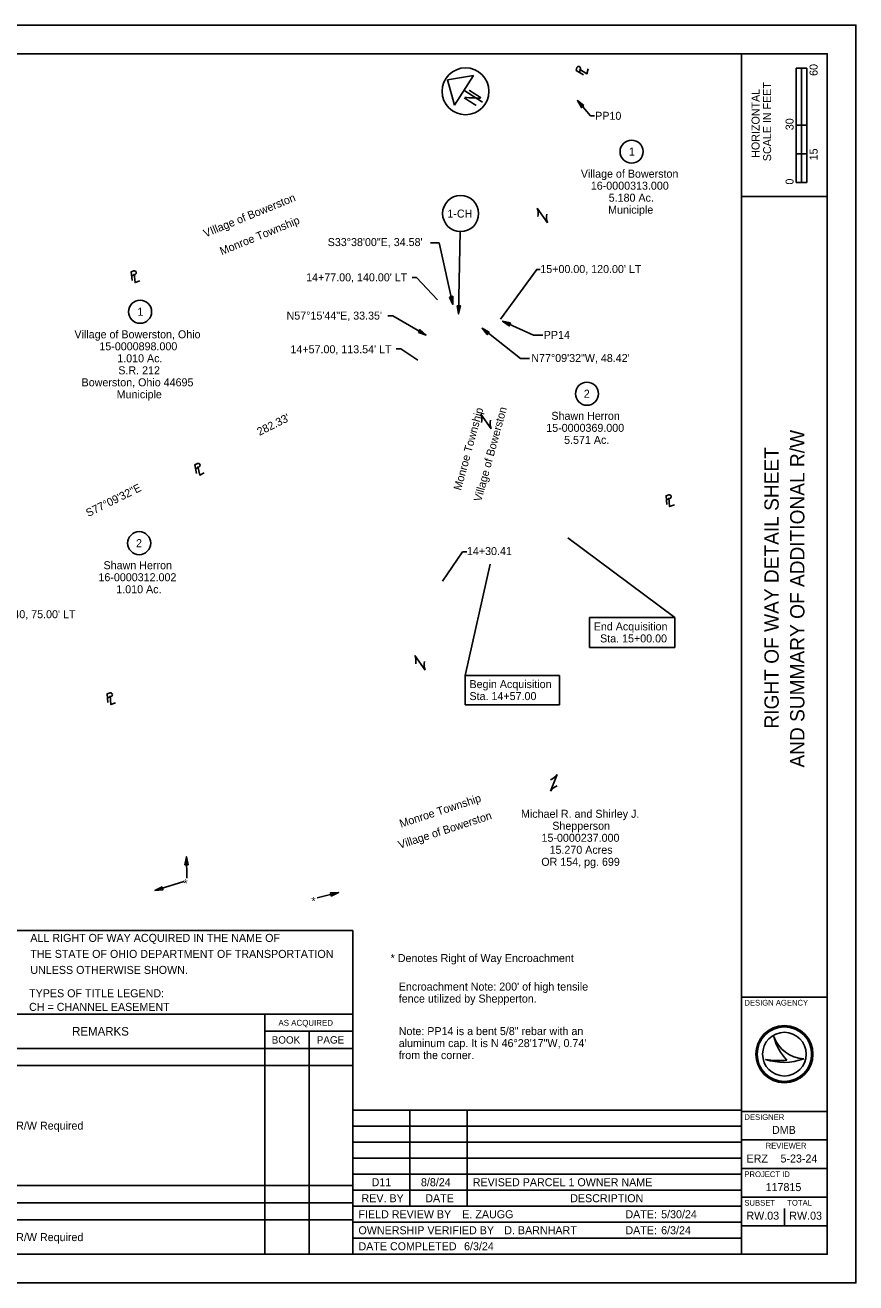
# Model space of a CAD drawing. Extents: x 0 to 1644, y -86 to 660.
# Drawn here: x 584 to 1020, y 0 to 660 of the extents above; entities that cross this region are included whole.
import ezdxf

# ---------------------------------------------------------------- set-up
doc = ezdxf.new("R2010")
doc.units = 0
for name, color, linetype in [('Default', 7, 'Continuous'), ('RW_X_Text', 7, 'Continuous'), ('SH_Border', 7, 'Continuous'), ('SH_Cut_Line', 7, 'Continuous'), ('SH_Data', 7, 'Continuous'), ('SH_Text', 7, 'Continuous'), ('UT_X_Water_Cells', 7, 'Continuous'), ('VG_X_Cells', 7, 'Continuous')]:
    doc.layers.add(name, color=color, linetype=linetype)

msp = doc.modelspace()

# ---------------------------------------------------------------- linework, layer by layer
at = {"layer": 'Default'}
for p, q in [((45, 184.85), (755.9, 184.85)), ((755.9, 184.85), (755.9, 60))]:
    msp.add_line(p, q, dxfattribs=at)
at = {"layer": 'SH_Border'}
for p, q in [((960, 15), (960, 645)), ((960, 570), (1005, 570)), ((960, 150), (1005, 150)), ((960, 90), (1005, 90)), ((960, 75), (1005, 75)), ((960, 60), (1005, 60)), ((960, 45), (1005, 45)), ((960, 30), (1005, 30))]:
    msp.add_line(p, q, dxfattribs=at)
msp.add_lwpolyline([(45, 645), (1005, 645), (1005, 15), (45, 15)], close=True, dxfattribs=at)
at = {"layer": 'SH_Cut_Line'}
msp.add_lwpolyline([(0, 0), (1020, 0), (1020, 660), (0, 660)], close=True, dxfattribs=at)
at = {"layer": 'SH_Data'}
for p, q in [((988.7, 577.5), (988.7, 637.5)), ((994.32, 637.5), (988.7, 637.5)), ((988.7, 607.5), (988.7, 637.5)), ((988.7, 637.5), (991.5, 637.5)), ((991.5, 637.5), (991.52, 637.5)), ((991.52, 637.5), (991.52, 607.5)), ((994.32, 637.5), (994.32, 577.5)), ((991.52, 607.5), (988.7, 607.5)), ((994.3, 607.5), (991.5, 607.5)), ((991.5, 607.5), (991.5, 592.5)), ((994.3, 592.5), (994.3, 607.5)), ((991.5, 592.5), (988.7, 592.5)), ((988.7, 592.5), (988.7, 577.5)), ((991.5, 577.5), (991.5, 592.5)), ((991.5, 592.5), (994.3, 592.5)), ((994.32, 577.5), (988.7, 577.5)), ((988.7, 577.5), (991.5, 577.5)), ((45, 141), (755.9, 141)), ((709.75, 141), (709.75, 15)), ((709.75, 132), (755.9, 132)), ((733, 132), (733, 15)), ((977.02, 129.29), (977.02, 129.29)), ((45, 123), (755.9, 123)), ((982.5, 120), (982.5, 120)), ((45, 114), (755.9, 114)), ((972.52, 117.29), (972.51, 117.29)), ((992.62, 117.56), (992.62, 117.56)), ((45, 51), (755.9, 51)), ((45, 42), (755.9, 42)), ((45, 33), (755.9, 33)), ((982.5, 30), (982.5, 39))]:
    msp.add_line(p, q, dxfattribs=at)
for radius in [15, 14.3, 14.3, 11.47]:
    msp.add_circle((982.5, 120), radius, dxfattribs=at)
for centre, radius, start, end in [((993.48, 134.93), 17.4, 198.92567, 198.93195), ((1000.4, 134.1), 23.87, 191.63793, 191.64215), ((993.48, 134.93), 17.4, 198.93195, 267.16574), ((1000.4, 134.1), 23.87, 191.64215, 226.09467), ((982.18, 146.1), 30.39, 251.45274, 251.45764), ((982.18, 146.1), 30.39, 251.45764, 290.08324), ((979.44, 154.63), 37.98, 259.49639, 259.49952), ((979.44, 154.63), 37.98, 259.49952, 276.66723)]:
    msp.add_arc(centre, radius, start, end, dxfattribs=at)
at = {"layer": 'SH_Text'}
for p, q in [((819.26, 633.61), (805.66, 631.34)), ((809.33, 618.05), (819.26, 633.61)), ((805.66, 631.34), (809.33, 618.05)), ((814.29, 625.83), (824.07, 619.58)), ((812.34, 551.65), (811.49, 508.45)), ((924.98, 349.08), (868.73, 391.04)), ((814.94, 318.8), (828.03, 377.17)), ((924.98, 349.08), (880.21, 349.08)), ((880.21, 349.08), (880.21, 333.46)), ((924.98, 349.08), (924.98, 333.46)), ((924.98, 333.46), (880.21, 333.46)), ((814.94, 318.8), (814.94, 303.27)), ((814.94, 318.8), (864.35, 318.8)), ((864.35, 318.8), (864.35, 303.27)), ((814.94, 303.27), (864.35, 303.27)), ((668.72, 212.36), (668.59, 223.62)), ((667.27, 210.55), (652.01, 205.85)), ((737.3, 202.04), (748.48, 204.83)), ((755.9, 90.6), (755.9, 15)), ((755.9, 90.6), (960, 90.6)), ((785.9, 90.6), (785.9, 40.2)), ((815.9, 90.6), (815.9, 40.2)), ((755.9, 82.2), (960, 82.2)), ((755.9, 73.8), (960, 73.8)), ((755.9, 65.4), (960, 65.4)), ((755.9, 57), (960, 57)), ((755.9, 48.6), (960, 48.6)), ((755.9, 40.2), (960, 40.2)), ((755.9, 31.8), (960, 31.8)), ((755.9, 23.4), (960, 23.4)), ((960, 15), (960, 15))]:
    msp.add_line(p, q, dxfattribs=at)
for points in [[(882.76, 612.49), (880.62, 612.46), (873.86, 620.46)], [(796.69, 545.71), (801.25, 545.71), (808.51, 513.42)], [(854.3, 531.81), (852.5, 531.81), (833.47, 505.75)], [(787.05, 527.55), (789.4, 527.55), (800.32, 515.83)], [(774.36, 507.49), (776.92, 507.49), (794.4, 497.39)], [(855.67, 497.35), (850.82, 497.35), (834.54, 504.66)], [(848.72, 485.02), (843.87, 485.02), (823.76, 500.92)], [(778.69, 490.07), (781.18, 490.07), (790.12, 484.19)], [(815.78, 383.56), (813.58, 383.56), (802.96, 368.29)]]:
    msp.add_lwpolyline(points, dxfattribs=at)
for points in [[(877.21, 617.79), (875.93, 616.71), (873.86, 620.46)], [(806.77, 517.34), (808.41, 517.71), (808.51, 513.42)], [(810.73, 512.66), (812.41, 512.63), (811.49, 508.45)], [(838.72, 503.7), (838.03, 502.17), (834.54, 504.66)], [(790.35, 498.76), (791.19, 500.22), (794.4, 497.39)], [(827.57, 498.97), (826.53, 497.66), (823.76, 500.92)], [(669.47, 219.43), (667.79, 219.41), (668.59, 223.62)], [(655.78, 207.89), (656.27, 206.29), (652.01, 205.85)], [(744.6, 203), (744.2, 204.63), (748.48, 204.83)]]:
    msp.add_lwpolyline(points, close=True, dxfattribs=at)
for centre, radius in [((815.11, 625.3), 12.3), ((902.26, 593.63), 6.05), ((812.52, 561.11), 9.46), ((644.27, 509.58), 6.05), ((878.85, 466.56), 6.05), ((643.77, 388.16), 6.05)]:
    msp.add_circle(centre, radius, dxfattribs=at)
at = {"layer": 'UT_X_Water_Cells'}
msp.add_circle((815.11, 625.3), 12.3, dxfattribs=at)
at = {"layer": 'VG_X_Cells'}
for p, q in [((874.94, 635.16), (875.45, 637.03)), ((876.16, 636.07), (876.16, 636.07)), ((858.1, 556.35), (852.74, 564.04)), ((855.42, 560.19), (855.42, 560.19)), ((639.81, 528.37), (641.61, 529.1)), ((641.27, 527.95), (641.27, 527.95)), ((828.54, 448.22), (823.18, 455.91)), ((825.86, 452.06), (825.86, 452.06)), ((673.43, 427.22), (675.17, 428.09)), ((674.92, 426.92), (674.92, 426.92)), ((920.54, 410.91), (922.37, 411.56)), ((921.98, 410.43), (921.98, 410.43)), ((793.93, 321.6), (788.57, 329.29)), ((791.25, 325.45), (791.25, 325.45)), ((627.2, 307), (629.04, 307.65)), ((628.65, 306.52), (628.65, 306.52)), ((859.71, 258.06), (863.19, 266.77)), ((861.45, 262.41), (861.45, 262.41))]:
    msp.add_line(p, q, dxfattribs=at)
for points in [[(877.08, 633.92), (873.1, 636.22), (873.51, 637.72)], [(874.88, 636.83), (878.84, 634.52), (879.53, 637.05)], [(640.12, 525.92), (639.53, 530.48), (640.97, 531.06)], [(641.1, 529.44), (641.67, 524.88), (644.1, 525.87)], [(673.93, 424.8), (673, 429.31), (674.39, 430)], [(674.64, 428.39), (675.55, 423.89), (677.9, 425.05)], [(920.74, 408.45), (920.36, 413.03), (921.82, 413.54)], [(921.88, 411.92), (922.24, 407.34), (924.71, 408.22)], [(627.41, 304.54), (627.03, 309.12), (628.49, 309.64)], [(628.55, 308.01), (628.91, 303.43), (631.38, 304.31)]]:
    msp.add_lwpolyline(points, dxfattribs=at)
for centre, radius, start, end in [((874.45, 637.3), 1.03, 345.18257, 156.03968), ((845.27, 561.16), 8.01, 348.40607, 21.04859), ((865.57, 559.23), 8.01, 168.40607, 201.04859), ((641.21, 530.05), 1.03, 292.59862, 103.45574), ((815.71, 453.03), 8.01, 348.40607, 21.04859), ((836.02, 451.1), 8.01, 168.40607, 201.04859), ((674.7, 429.01), 1.03, 296.90724, 107.76435), ((922.02, 412.53), 1.03, 289.9764, 100.83351), ((781.1, 326.41), 8.01, 348.40607, 21.04859), ((801.4, 324.48), 8.01, 168.40607, 201.04859), ((628.68, 308.62), 1.03, 289.9764, 100.83351), ((856.69, 271.43), 8.01, 291.70234, 324.34487), ((866.22, 253.4), 8.01, 111.70234, 144.34487)]:
    msp.add_arc(centre, radius, start, end, dxfattribs=at)

# ---------------------------------------------------------------- texts
at = {"layer": 'RW_X_Text'}
for s, p in [('TYPES OF TITLE LEGEND:', (640.49, 175.85)), ('SH = STANDARD HIGHWAY EASEMENT', (640.49, 175.82)), ('T = TEMPORARY EASEMENT', (640.49, 175.78))]:
    msp.add_text(s, height=0.021, dxfattribs=at).set_placement(p)
at = {"layer": 'SH_Data'}
for s, height, rotation, p in [('60', 4.2, 90, (999.91, 633.37)), ('SCALE IN FEET', 4.2, 90, (975.52, 588.62)), ('HORIZONTAL', 4.2, 90, (969.45, 590.38)), ('30', 4.2, 90, (987.31, 604.87)), ('15', 4.2, 90, (999.91, 589.06)), ('0', 4.2, 90, (987.31, 576.34)), ('AND SUMMARY OF ADDITIONAL R/W', 7.5, 90, (993, 270.4)), ('RIGHT OF WAY DETAIL SHEET', 7.5, 90, (979.5, 290.87)), ('REMARKS', 4.5, 360, (608.59, 129.75)), ('AS ACQUIRED', 3.1083, 360, (716.88, 134.9)), ('BOOK', 3.866, 360, (713.37, 125.54)), ('PAGE', 3.866, 360, (737.02, 125.57))]:
    msp.add_text(s, height=height, rotation=rotation, dxfattribs=at).set_placement(p)
for s, height, p in [('DESIGN AGENCY', 3, (961.5, 145.5)), ('DESIGNER', 3, (961.5, 85.5)), ('DMB', 4.2, (975.98, 78.15)), ('REVIEWER', 3, (972.65, 70.5)), ('ERZ', 4.2, (962.61, 63.15)), ('5-23-24', 4.2, (980.44, 63.15)), ('PROJECT ID', 3, (961.5, 55.5)), ('117815', 4.2, (972.64, 48.15)), ('SUBSET', 3, (961.5, 40.5)), ('TOTAL', 3, (984, 40.5)), ('RW.03', 4.2, (962.55, 33.15)), ('RW.03', 4.2, (985.05, 33.15))]:
    msp.add_text(s, height=height, dxfattribs=at).set_placement(p)
at = {"layer": 'SH_Text'}
for s, height, rotation, p in [('N', 7.5, 57.43952, (820.04, 616.78)), ('VIllage of Bowerston', 4.2, 22.12764, (678.56, 548.55)), ('Monroe Township', 4.2, 22.12764, (687.14, 539.24)), ("282.33'", 4.2, 26.43626, (706.91, 444.47)), ('Monroe Township', 4.2, 74.71158, (812.73, 415.58)), ('Village of Bowerston', 4.2, 74.71158, (823.34, 409.64)), ('S77°09\'32"E', 4.2, 26.43626, (617.08, 401.81)), ('Monroe Township', 4.2, 18.00786, (781.22, 238.85)), ('Village of Bowerston', 4.2, 18.00786, (780.55, 227.72))]:
    msp.add_text(s, height=height, rotation=rotation, dxfattribs=at).set_placement(p)
for s, p in [('PP10', (883.16, 610.33)), ('1', (900.85, 591.53)), ('Village of Bowerston', (875.64, 579.95)), ('16-0000313.000', (880.87, 573.65)), ('5.180 Ac.', (890.26, 567.35)), ('1-CH', (805.58, 559.01)), ('Municiple', (889.94, 561.05)), ('S33°38\'00"E, 34.58\'', (742.75, 544.06)), ("14+77.00, 140.00' LT", (731.43, 525.56)), ("15+00.00, 120.00' LT", (854.36, 529.91)), ('1', (642.86, 507.48)), ('N57°15\'44"E, 33.35\'', (721.15, 505.48)), ('Village of Bowerston, Ohio', (609.8, 495.67)), ('PP14', (856.16, 495.33)), ('15-0000898.000', (622.88, 489.37)), ("14+57.00, 113.54' LT", (723.2, 487.82)), ('1.010 Ac.', (632.27, 483.07)), ('N77°09\'32"W, 48.42\'', (849.62, 483.22)), ('S.R. 212', (632.83, 476.77)), ('Bowerston, Ohio 44695', (613.56, 470.47)), ('2', (877.2, 464.46)), ('Municiple', (631.95, 464.17)), ('Shawn Herron', (860.17, 452.88)), ('15-0000369.000', (857.46, 446.58)), ('5.571 Ac.', (866.85, 440.28)), ('2', (642.12, 386.06)), ('14+30.41', (815.83, 381.92)), ('Shawn Herron', (625.09, 374.48)), ('16-0000312.002', (622.39, 368.18)), ('1.010 Ac.', (631.77, 361.88)), ("11+71.40, 75.00' LT", (560.39, 348.79)), ('End Acquisition', (882.4, 342.38)), ('Sta. 15+00.00', (885.73, 336.08)), ('Begin Acquisition', (817.18, 312.11)), ('Sta. 14+57.00', (817.18, 305.81)), ('Michael R. and Shirley J.', (844.23, 244.05)), ('Shepperson', (860.64, 237.75)), ('15-0000237.000', (854.99, 231.45)), ('15.270 Acres', (859.2, 225.15)), ('OR 154, pg. 699', (854.87, 218.85)), ('*', (667, 207.57)), ('*', (734.18, 198.26)), ('ALL RIGHT OF WAY ACQUIRED IN THE NAME OF', (586.64, 178.92)), ('THE STATE OF OHIO DEPARTMENT OF TRANSPORTATION', (586.64, 170.52)), ('* Denotes Right of Way Encroachment', (775.79, 168.34)), ('UNLESS OTHERWISE SHOWN.', (586.64, 162.12)), ('TYPES OF TITLE LEGEND:', (586, 149.86)), ("Encroachment Note: 200' of high tensile", (780.04, 153.37)), ('CH = CHANNEL EASEMENT', (586, 142.72)), ('fence utilized by Shepperton.', (780.04, 147.07)), ('Note: PP14 is a bent 5/8" rebar with an', (780.04, 130.01)), ('aluminum cap. It is N 46°28\'17"W, 0.74\'', (780.04, 123.71)), ('from the corner.', (780.04, 117.41)), ('No Additional R/W Required', (544.25, 80.4)), ('D11', (765.81, 50.7)), (' 8/8/24 ', (790.13, 50.7)), ('REVISED PARCEL 1 OWNER NAME           ', (818.9, 50.7)), ('REV. BY', (760.5, 42.3)), ('DATE', (793.98, 42.3)), ('DESCRIPTION', (870.05, 42.3)), ('FIELD REVIEW BY', (758.9, 33.9)), ('E. ZAUGG                ', (813.39, 33.9)), ('DATE:', (899.02, 33.9)), ('5/30/24 ', (917.79, 33.9)), ('OWNERSHIP VERIFIED BY', (758.9, 25.5)), ('D. BARNHART      ', (835.44, 25.5)), ('DATE:', (899.02, 25.5)), ('6/3/24  ', (917.79, 25.5)), ('No Additional R/W Required', (544.25, 21.9)), ('DATE COMPLETED', (758.9, 17.1)), ('6/3/24                             ', (814.33, 17.1))]:
    msp.add_text(s, height=4.2, dxfattribs=at).set_placement(p)

doc.saveas('drawing.dxf')
